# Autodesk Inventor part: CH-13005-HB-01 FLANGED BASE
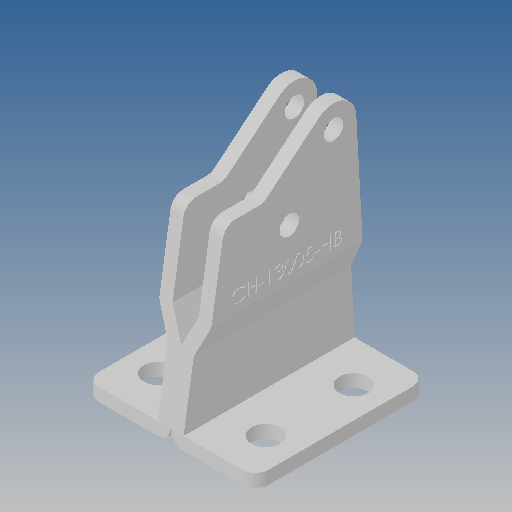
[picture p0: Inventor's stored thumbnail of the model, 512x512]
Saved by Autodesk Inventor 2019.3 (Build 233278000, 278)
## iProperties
Created: 2012-09
Part Number: CH-13005-HB-01 FLANGED BASE
Material: Ogólny
Document SubType Name: Modeling
Designer: CADENGINEERING4
Density: 1 g/cm^3
Appearance: Domyślna
Author: CADENGINEERING4
Revision Number: ÈÎºÎ
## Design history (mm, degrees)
feature "ÇÐ³ý-À­Éì3"
feature "ÇÐ³ý-À­Éì6"
node "Bryła1"
node "Bryła2"
